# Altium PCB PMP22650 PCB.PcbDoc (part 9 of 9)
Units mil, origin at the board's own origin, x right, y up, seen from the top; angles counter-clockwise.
Board outline 11311 x 5233 mil, 8 copper layers (Layer 1, Layer 2, Layer 3, Layer 4, Layer 5, Layer 6, Layer 7, Layer 8), stack 88.6 mil thick; 633 components, 410 nets, 2503 pads, 1993 vias.
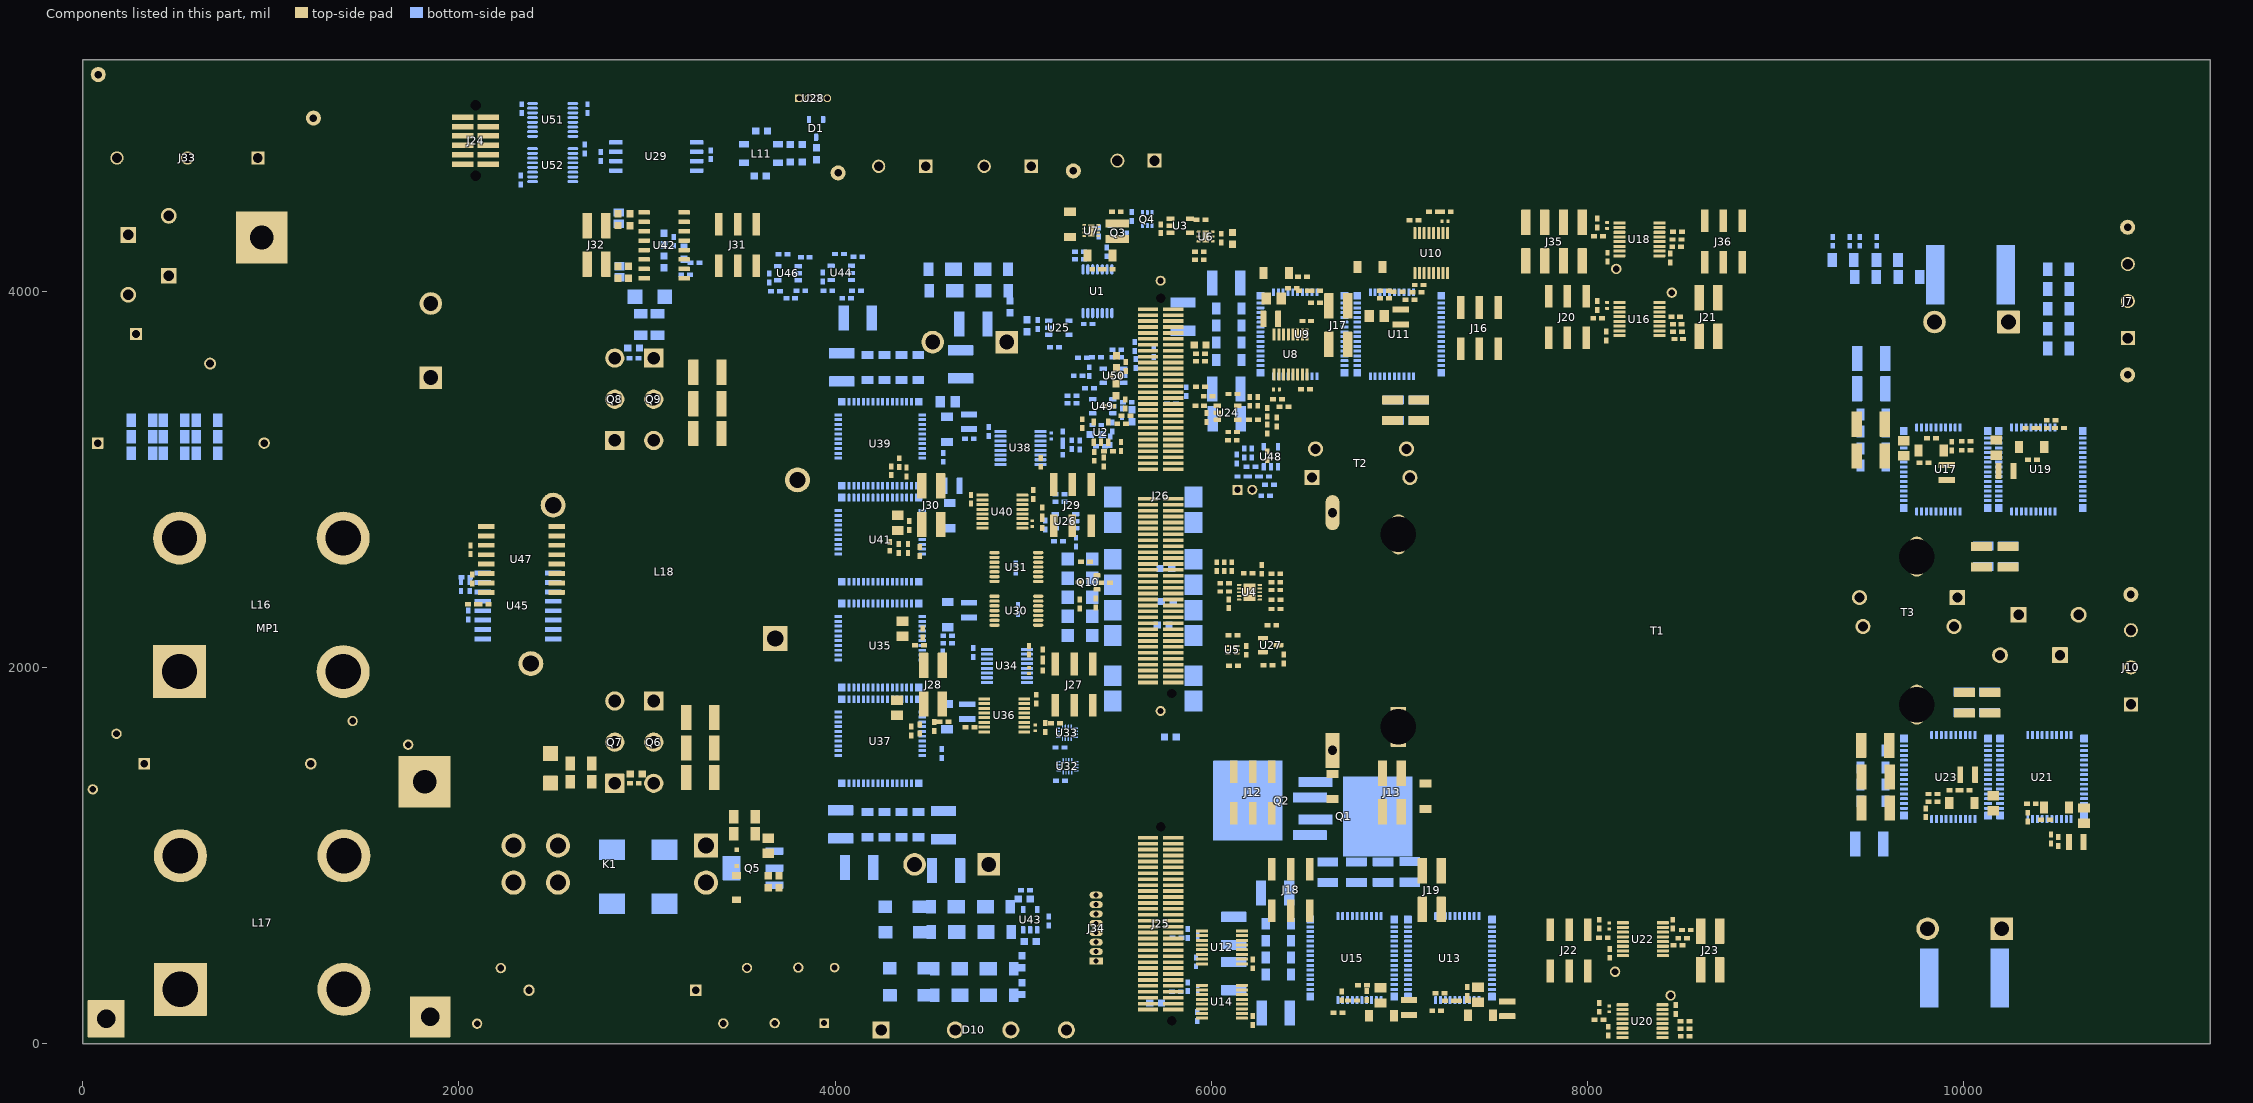
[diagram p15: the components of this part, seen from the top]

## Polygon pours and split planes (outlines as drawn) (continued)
SW_C_RES on Layer 2 "NONET_L-01_P-001" (solid, remove dead copper, pour order 366): 10325.29,2450 9913.23,2450 9913.23,2604 10324.97,2604

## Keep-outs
Layer 1:
  circle w1: c7548.54,327.29 r10
  circle w1: c7527.27,327.29 r10
  circle w1: c6310,412 r10
  circle w1: c6291,412 r10
  circle w1: c6273,412 r10
  circle w1: c6310,504 r10
  circle w1: c6291,505 r10
  circle w1: c6273,505 r10
  circle w1: c6273,593 r10
  circle w1: c6291,593 r10
  circle w1: c6310,593 r10
  circle w19.68: c4665.9,2514.99 r98.43
  circle w19.68: c3813.46,647.46 r98.43
  circle w19.68: c3379.18,3901.84 r98.43
  circle w19.68: c1247.18,3089.84 r98.43
  circle w19.68: c10471.89,2626.17 r98.43
  circle w19.68: c7448.57,4317.63 r98.43
  circle w19.68: c9104.8,145.99 r98.43
  circle w19.68: c6029.84,891.93 r98.43
  circle w19.68: c6343.43,2734.37 r98.43
  circle w19.68: c6576.2,3348.75 r98.43
  circle w19.68: c7800.73,214.14 r98.43
  circle w19.68: c6285.57,1786.37 r98.43
  circle w19.68: c9071.27,4171.97 r98.43
  circle w19.68: c10392.8,1838.99 r98.43
Layer 3:
  circle w1: c8447.91,3994.61 r30
  circle w1: c4352.81,2310.97 r10
  circle w1: c4352.81,2289.69 r10
  circle w1: c4422,2171 r10
  circle w1: c4343,2131.24 r10
  circle w1: c4365.27,2131.24 r10
  circle w1: c4413.27,2024.28 r10
  circle w1: c4413.27,2001.49 r10
  circle w1: c6275,688 r10
  circle w1: c6257,688 r10
  circle w1: c6257,664 r10
  circle w1: c6309,412 r10
  circle w1: c6292,412 r10
  circle w1: c6273,412 r10
  circle w1: c6309,504 r10
  circle w1: c6292,504 r10
  circle w1: c6273,504 r10
  circle w1: c6273,593 r10
  circle w1: c6291,593 r10
  circle w1: c6310,593 r10
  circle w1: c9258.27,4167.6 r7
Layer 5:
  circle w1: c10457.46,1232.86 r10
  circle w1: c10457.24,1252.37 r10
  circle w1: c10606.27,1303.88 r10
  circle w1: c10584.99,1303.88 r10
  circle w1: c7264.16,750.08 r10
  circle w1: c7264.16,771.71 r10
  circle w1: c4352.81,2310.97 r10
  circle w1: c4352.81,2289.69 r10
  circle w1: c4638.27,3332.6 r10
  circle w1: c4638.27,3352.6 r10
  circle w1: c4468.97,3067.17 r10
  circle w1: c4424.17,3214 r10
  circle w1: c4658.27,3332.6 r10
  circle w1: c4658.27,3352.6 r10
  circle w1: c4424.17,3308.36 r10
  circle w1: c4424.17,3262 r10
  circle w1: c4426,3117 r10
  circle w1: c4448.09,3067.17 r10
  circle w1: c4761,1948 r10
  circle w1: c4762,2098 r10
  circle w1: c4343,2131.24 r10
  circle w1: c4365.27,2131.24 r10
  circle w1: c4413.27,2024.28 r10
  circle w1: c4413.27,2001.49 r10
  circle w1: c10572,1132 r10
  circle w1: c10551,1132 r10
  circle w1: c10314,1196 r10
  circle w1: c10477.46,1232.86 r10
  circle w1: c10477.24,1252.37 r10
  circle w1: c7443,344 r10
  circle w1: c7443,365 r10
  circle w1: c7306,271 r10
  circle w1: c7249,306 r10
  circle w1: c6219,581 r10
  circle w1: c6241,450 r10
  lines w1: 4431.7,2173.43 ccw(c4422,2171) 4431.95,2172 ; 4648.97,2341.06 ccw(c4639.27,2338.63) 4649.22,2339.63 ; 4648.97,2363.85 ccw(c4639.27,2361.43) 4649.22,2362.42 ; 4667.7,2341.43 ccw(c4658,2339) 4667.95,2340 ; 4667.7,2364.43 ccw(c4658,2362) 4667.95,2363
Layer 6:
  circle w1: c10457.46,1232.86 r10
  circle w1: c10457.24,1252.37 r10
  circle w1: c9850.69,3174.56 r10
  circle w1: c8655,3689 r10
  circle w1: c8655,3710 r10
  circle w1: c8423,3791 r10
  circle w1: c8426,3945 r10
  circle w1: c10584.99,1303.88 r10
  circle w1: c10606.27,1303.88 r10
  circle w1: c7264.16,771.71 r10
  circle w1: c7264.16,750.08 r10
  circle w1: c4325.4,2310.97 r10
  circle w1: c4325.4,2289.69 r10
  circle w1: c8442,59 r10
  circle w1: c8491,209 r10
  circle w1: c8745,432 r10
  circle w1: c8745,452 r10
  circle w1: c10314.51,1195.86 r10
  circle w1: c10572.48,1132.31 r10
  circle w1: c10551,1132 r10
  circle w1: c10477.46,1232.86 r10
  circle w1: c10477.24,1252.37 r10
  circle w1: c9990,3231 r10
  circle w1: c9851,3199 r10
  circle w1: c9723,3157 r10
  circle w1: c9723,3135 r10
  circle w1: c7443,344 r10
  circle w1: c7443,365 r10
  circle w1: c7249,306 r10
  circle w1: c6241,450 r10
  circle w1: c8655,4132 r7
  circle w1: c8752,4132 r7
Layer 2:
  circle w1: c4352.81,2289.69 r10
  circle w1: c4352.81,2310.97 r10
  circle w1: c4638.27,3352.6 r10
  circle w1: c4658.27,3352.6 r10
  circle w1: c4658.27,3332.6 r10
  circle w1: c4638.27,3332.6 r10
  circle w1: c4468.97,3067.17 r10
  circle w1: c4448.09,3067.17 r10
  circle w1: c4426,3117 r10
  circle w1: c4424.17,3214 r10
  circle w1: c4424.17,3262 r10
  circle w1: c4424.17,3308.36 r10
  circle w1: c4639.27,2338.63 r10
  circle w1: c4639.27,2361.43 r10
  circle w1: c4658,2362 r10
  circle w1: c4658,2339 r10
  circle w1: c4761,2097 r10
  circle w1: c4413.27,2001.49 r10
  circle w1: c4413.27,2024.28 r10
  circle w1: c4343,2131.24 r10
  circle w1: c4365.27,2131.24 r10
  circle w1: c4422,2171 r10
Layer 7:
  circle w1: c7264.16,771.71 r10
  circle w1: c7264.16,750.08 r10
  circle w1: c6241,450 r10
Layer 8:
  circle w1: c6219,581 r10
  circle w1: c6241,450 r10
  circle w29.53: c6576.2,3348.75 r103.35
  circle w29.53: c4665.9,2514.99 r103.35
  circle w29.53: c3813.46,647.46 r103.35
  circle w29.53: c3379.18,3901.84 r103.35
  circle w29.53: c1247.18,3089.84 r103.35
  circle w29.53: c10471.89,2626.17 r103.35
  circle w29.53: c7448.57,4317.63 r103.35
  circle w29.53: c9104.8,145.99 r103.35
  circle w29.53: c6029.84,891.93 r103.35
  circle w29.53: c6343.43,2734.37 r103.35
  circle w29.53: c7800.73,214.14 r103.35
  circle w29.53: c6285.57,1786.37 r103.35
  circle w29.53: c9071.27,4171.97 r103.35
  circle w29.53: c10392.8,1838.99 r103.35
Keep-Out Layer:
  circle w25: c4665.9,2514.99 r75.51
  circle w25: c3813.46,647.46 r75.51
  circle w25: c3379.18,3901.84 r75.51
  circle w25: c1247.18,3089.84 r75.51
  circle w25: c10471.89,2626.17 r75.51
  circle w25: c7448.57,4317.63 r75.51
  circle w25: c9104.8,145.99 r75.51
  circle w25: c6285.57,1786.37 r75.51
  circle w23.62: c10551.18,118.11 r55.12
  circle w23.62: c10551.18,4330.71 r55.12
  circle w25: c6029.84,891.93 r75.51
  circle w25: c6343.43,2734.37 r75.51
  circle w25: c6576.2,3348.75 r75.51
  circle w25: c7800.73,214.14 r75.51
  circle w25: c9071.27,4171.97 r75.51
  circle w25: c10392.8,1838.99 r75.51
  text ".Layer_Name" at 577,-858.49 h60

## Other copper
Layer 1:
  text ".Layer_Name" at 577,-858.49 h60
Layer 3:
  pour cut-out: 6657,4191 6657,4187 6272,4187 6272,3760 6307,3725 6611,3725 6657,3771 6657,4191 6661,4191 6661,3770 6612,3721 6305,3721 6268,3758 6268,4191
  pour cut-out: 6667,704 6667,698 6135,698 6133,371 6660.03,371 6705.87,416.84 7125.38,416.84 7125.38,113.84 7520.5,105.53 7523.57,289.8 7504,344.17 7504,653 7330.28,826.72 6666.99,831.64 6667,704 6657.84,705 6657.84,836.84 7332.74,835.52 7510.13,658.13 7510.13,349.52 7529.35,293.97 7529.35,96.68 7117.07,105.53 7115.29,406.75 6707.84,406.75 6662.29,363.99 6129,363 6129,704
  region net PGND: 5542,3698.08
  region net PGND: 5542,3698.08
  region net PGND: 5542,3698.08
  region net PGND: 5542,3698.08
  region net PGND: 5542,3698.08
  region net PGND: 5542,3698.08
  region net PGND: 5542,3698.08
  region net PGND: 5542,3698.08
  region net PGND: 5542,3698.08
  region net PGND: 5542,3698.08
  region net PGND: 5542,3698.08
  region net PGND: 5542,3698.08
  region net PGND: 5542,3698.08
  region net PGND: 5542,3698.08
  region net PGND: 5542,3698.08
  region net PGND: 5542,3698.08
  region net PGND: 5542,3698.08
  region net PGND: 5542,3698.08
  region net PGND: 5542,3698.08
  region net PGND: 5542,3698.08
  region net PGND: 5542,3698.08
  region net PGND: 5542,3698.08
  region net PGND: 5542,3698.08
  region net PGND: 5542,3698.08
  region net PGND: 5542,3698.08
  region net PGND: 5542,3698.08
  region net PGND: 5542,3698.08
  region net PGND: 5542,3698.08
  region net PGND: 5542,3698.08
  region net PGND: 5542,3698.08
  region net PGND: 5542,3698.08
  region net PGND: 5542,3698.08
  region net PGND: 5542,3698.08
  region net PGND: 5542,3698.08
  region net PGND: 5542,3698.08
  region net PGND: 5542,3698.08
  region net PGND: 5542,3698.08
  region net PGND: 5542,3698.08
  region net PGND: 5542,3698.08
  region net PGND: 5542,3698.08
  region net PGND: 5542,3698.08
  region net PGND: 5542,3698.08
  region net PGND: 5542,3698.08
  region net PGND: 5542,3698.08
  region net PGND: 5542,3698.08
  region net PGND: 5542,3698.08
  region net PGND: 5542,3698.08
  region net PGND: 5542,3698.08
  region net PGND: 5542,3698.08
  region net PGND: 5542,3698.08
  region net PGND: 5542,3698.08
  region net PGND: 5542,3698.08
  region net PGND: 5542,3698.08
  region net PGND: 5542,3698.08
  region net PGND: 5542,3698.08
  region net PGND: 5542,3698.08
  region net PGND: 5542,3698.08
  region net PGND: 5542,3698.08
  region net PGND: 5542,3698.08
  region net PGND: 5542,3698.08
  region net PGND: 5542,3698.08
  region net PGND: 5542,3698.08
  region net PGND: 5542,3698.08
  region net PGND: 5542,3698.08
  region net PGND: 5542,3698.08
  region net PGND: 5542,3698.08
  region net PGND: 5542,3698.08
  region net PGND: 5542,3698.08
  region net PGND: 5542,3698.08
  region net PGND: 5542,3698.08
  region net PGND: 5542,3698.08
  region net PGND: 5542,3698.08
  region net PGND: 5542,3698.08
  region net PGND: 5542,3698.08
  region net PGND: 5542,3698.08
  region net PGND: 5542,3698.08
  region net PGND: 5542,3698.08
  region net PGND: 5542,3698.08
  region net PGND: 5542,3698.08
  region net PGND: 5542,3698.08
  region net PGND: 5542,3698.08
  region net PGND: 5542,3698.08
  region net PGND: 5542,3698.08
  region net PGND: 5542,3698.08
  region net PGND: 5542,3698.08
  region net PGND: 5542,3698.08
  region net PGND: 5542,3698.08
  region net PGND: 5542,3698.08
  region net PGND: 5542,3698.08
  region net PGND: 5542,3698.08
  region net PGND: 5542,3698.08
  region net PGND: 5542,3698.08
  region net PGND: 5542,3698.08
  region net PGND: 5542,3698.08
  region net PGND: 5542,3698.08
  region net PGND: 5542,3698.08
  region net PGND: 5542,3698.08
  region net PGND: 5542,3698.08
  region net PGND: 5542,3698.08
  region net PGND: 5542,3698.08
  region net PGND: 5542,3698.08
  region net PGND: 5542,3698.08
  region net PGND: 5542,3698.08
  region net PGND: 5542,3698.08
  region net PGND: 5542,3698.08
  region net PGND: 5542,3698.08
  region net PGND: 5542,3698.08
  region net PGND: 5542,3698.08
  region net PGND: 5542,3698.08
  region net PGND: 5542,3698.08
  region net PGND: 5542,3698.08
  region net PGND: 5542,3698.08
  region net PGND: 5542,3698.08
  region net PGND: 5542,3698.08
  region net PGND: 5542,3698.08
  region net PGND: 5542,3698.08
  region net PGND: 5542,3698.08
  region net PGND: 5542,3698.08
  region net PGND: 5542,3698.08
  region net PGND: 5542,3698.08
  region net PGND: 5542,3698.08
  region net PGND: 5542,3698.08
  region net PGND: 5542,3698.08
  region net PGND: 5542,3698.08
  region net PGND: 5542,3698.08
  region net PGND: 5542,3698.08
  region net PGND: 5542,3698.08
  region net PGND: 5542,3698.08
  region net PGND: 5542,3698.08
  region net PGND: 5542,3698.08
Layer 4:
  pour cut-out: 4446.18,1892.05 4758.18,1892.05 4851,1799.24 4851,1655.87 4709.18,1514.05 4363.18,1514.05 4363.18,1809.05
  pour cut-out: 4413,2967.5 4725,2967.5 4781,2911.5 4781,2694.5 4676,2589.5 4330,2589.5 4263,2656.5 4263,2817.5
  pour cut-out: 6638.18,283.48 6680.37,325.67 6950.98,325.67 6990.17,286.48 6990.17,130.48 6960.17,100.48 6661.17,100.48 6638.17,123.48
  pour cut-out: 6779.18,4068.48 6821.37,4110.67 7091.98,4110.67 7131.17,4071.48 7131.17,3915.48 7101.17,3885.48 6802.17,3885.48 6779.17,3908.48
  pour cut-out: 10180.5,3357 10222.69,3399.19 10493.31,3399.19 10532.5,3360 10532.5,3204 10413.5,3085 10237,3085 10180.5,3141.5
  pour cut-out: 9808,1284 9881,1357 10090,1357 10160,1287 10160,1131 10130,1101 9831,1101 9808,1124
Layer 5:
  pour cut-out: 4430.37,1878.31 4742.37,1878.31 4853,1767.68 4853,1659.95 4693.37,1500.31 4347.37,1500.31 4347.37,1795.31
  pour cut-out: 4428,2965.77 4740,2965.77 4796,2909.77 4796,2692.77 4691,2587.77 4345,2587.77 4278,2654.77 4278,2815.77
  pour cut-out: 6779.18,4068.48 6821.37,4110.67 7091.98,4110.67 7131.17,4071.48 7131.17,3915.48 7101.17,3885.48 6802.17,3885.48 6779.17,3908.48
  pour cut-out: 10180.5,3357 10222.69,3399.19 10493.31,3399.19 10532.5,3360 10532.5,3204 10416.5,3088 10243,3088 10180.5,3150.5
  pour cut-out: 9808,1284 9879,1355 10092,1355 10160,1287 10160,1131 10130,1101 9831,1101 9808,1124
Layer 6:
  pour cut-out: 6779.18,4068.48 6821.37,4110.67 7091.98,4110.67 7131.17,4071.48 7131.17,3915.48 7101.17,3885.48 6802.17,3885.48 6779.17,3908.48
  pour cut-out: 10180.5,3357 10222.69,3399.19 10493.31,3399.19 10532.5,3360 10532.5,3204 10413.5,3085 10242,3085 10180.5,3146.5
  pour cut-out: 9808,1284 9881,1357 10090,1357 10160,1287 10160,1131 10130,1101 9831,1101 9808,1124
Layer 8:
  pour cut-out: 4304,3072 4304,3309 cw(c4316,3309) 4328,3309 4328,3072 cw(c4316,3072)
  pour cut-out: 4294,2598 4294,2835 cw(c4306,2835) 4318,2835 4318,2598 cw(c4306,2598)
  pour cut-out: 4290,2003 4290,2240 cw(c4302,2240) 4314,2240 4314,2003 cw(c4302,2003)
  pour cut-out: 4318,1502 4318,1739 cw(c4330,1739) 4342,1739 4342,1502 cw(c4330,1502)
  pour cut-out: 7202,408 7439,408 cw(c7439,396) 7439,384 7202,384 cw(c7202,396)
  pour cut-out: 6640,367 6877,367 cw(c6877,355) 6877,343 6640,343 cw(c6640,355)
  pour cut-out: 6852,3872 7089,3872 cw(c7089,3860) 7089,3848 6852,3848 cw(c6852,3860)
  pour cut-out: 6340,3877 6577,3877 cw(c6577,3865) 6577,3853 6340,3853 cw(c6340,3865)
  pour cut-out: 9803,3122 10040,3122 cw(c10040,3110) 10040,3098 9803,3098 cw(c9803,3110)
  pour cut-out: 10262,3110 10499,3110 cw(c10499,3098) 10499,3086 10262,3086 cw(c10262,3098)
  pour cut-out: 9780.4,1376.13 10017.4,1376.14 cw(c10017.4,1364.14) 10017.4,1352.14 9780.4,1352.14 cw(c9780.4,1364.13)
  pour cut-out: 10305,1338 10542,1338 cw(c10542,1326) 10542,1314 10305,1314 cw(c10305,1326)
  text ".Layer_Name" at 577,-858.49 h60

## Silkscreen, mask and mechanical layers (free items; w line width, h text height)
Top Overlay:
  lines w10: 0,4448.82 0,0 10669.29,0 ; 0.71,4449.52 10670,4449.52 10670,0.71 ; 242,3983 242,4156 ; 456,4225 456,4402 ; 4094,4998 4094,5209 4364,5209 5136,5209 5470,5209 6001,5209 6001,4910 5372,4910 5372,5081 ; 4095,4995 5295,4995 5295,5016.5 5295,5081 6001,5081 ; 5721,2560 5722,2561 ; 5942,1904 5942,1633 6125,1633 ; 5945,1905 6127,1905 6127,1734 6127,1635 ; 6126,1904 6394,2172 6394,2292 ; 10187,2069 10364,2069 ; 10433,2283 10606,2283 ; 11302,1692 11120,1692 11120,1863 11120,4559 11305,4559 11305,1693 ; 6394,2292 6397,2295 6397,2525 6396,2526 6287,2526 6287,2292 6394,2292 ; 25,5023 25,5215 196,5215 1963,5215 1963,5023 25,5023
  text "90 VAC - 265 VAC, 50 Hz -60 Hz" at 163,5127.99 h60
  text "250 VDC - 450 VDC, 6600 W, 30 A" at 4147,5120.99 h60
  text "CAN" at 3800,5103 h60
  text "6600 W, 30 A" at 1173,5040.99 h60
  text "LINE" at 31,5032 h60
  text "NEUTRAL" at 310,5032 h60
  text "EARTH" at 739,5032 h60
  text "ETAS" at 1987,5032 h60
  text "DCLINK" at 4198,5012 h60
  text "PGND" at 4775,5012 h60
  text "+" at 4121,5002 h60
  text "+" at 4552.04,5002 h60
  text "-" at 4685.35,5002 h60
  text "-" at 5056,5002 h60
  text "12 V, 2 A" at 5401,4982.99 h60
  text "-" at 5493.26,4905 h60
  text "+" at 5671,4905 h60
  text "'.PRJ_Number'.PCB_Rev" at 9668,4850 h108.27
  text "NEUTRAL" at 1330.27,4820.6 h60
  text "PMP22712" at 3591,4317 h45
  text "PMP22773" at 8912.52,4305.85 h45
  text "-" at 11184.25,4124 h60 r90
  text "BATT_RTN" at 11268.51,4080.1 h60 r90
  text "-" at 11184.25,3923.5 h60 r90
  text "PMP22712" at 8770,3756 h45
  text "PMP22712" at 6831.57,3736.49 h45
  text "-" at 11184.25,3723 h60 r90
  text "SGND" at 10835,3421 h60
  text "PMP22712" at 4666,2672 h45
  text "+" at 11134.27,2167.6 h60
  text "250 VDC - 450 VDC, 6600 W, 30 A" at 11276.01,2097 h60 r90
  text "+" at 11134.27,1967.17 h60
  text "PMP22712" at 4645,1865 h45
  text "+" at 11134.27,1766.73 h60
  text "VBATT" at 11281,1737 h60 r90
  text "PMP22742" at 6421,1293 h45
  text "PMP22712" at 6699,809 h45
  text "PMP22712" at 8802,481 h45
  text ".Layer_Name" at 577,-858.49 h60
Bottom Overlay:
  lines w10: 0,4448.82 0,0 10669.29,0 ; 0.71,4449.52 10670,4449.52 10670,0.71
  text ".Layer_Name" at 577,-858.49 h60
Top Paste:
  text ".Layer_Name" at 577,-858.49 h60
Bottom Paste:
  text ".Layer_Name" at 577,-858.49 h60
Top Solder:
  text ".Layer_Name" at 577,-858.49 h60
  text ".Layer_Name" at 577,-858.49 h60
Bottom Solder:
  text ".Layer_Name" at 577,-858.49 h60
Drill Guide:
  text ".Layer_Name" at 577,-858.49 h60
M1 Board Outline:
  drawing of 328 lines, arcs and shapes, not listed
  text ".Layer_Name" at 577,-858.49 h60
M2 Board Dimensions:
  rectangle: 0,-275 125,-150
  rectangle: 125,-400 500,-275
  lines w7: 0,-275 1000,-275 ; 125,-400 125,-150 ; 250,-400 250,-150 ; 500,-400 500,-150 ; 750,-400 750,-150 ; 0,-400 1000,-400 1000,-150 0,-150 0,-400
  text ".Layer_Name" at 577,-858.49 h60
M3 3D STEP Top:
  text ".Layer_Name" at 577,-858.49 h60
M4 3D STEP Bottom:
  text ".Layer_Name" at 577,-858.49 h60
M5 Assembly Top:
  circle w10: c1259.84,1129.08 r39.37
  circle w10: c1254.1,4902.46 r39.37
  lines w10: -292,-930.17 6308,-930.17 ; -292,-726.83 6310,-726.83 ; -292,-523.5 -292,-1133.5 3713,-1133.5 6310,-1133.5 6310,-523.5 -291.5,-523.5 -291.5,-1133.5 1284,-1133.5 ; 2173,-1133.5 2173,-523.5 ; 3440,-726.83 3440,-523.5 ; 4280,-726.83 4280,-523.5 ; 4902,-1140 4902,-937.17 ; 7050,3043 7053,3043 ; 7445,3043 7445,2808 8970,2808 8969,2809 8969,3197 7445,3197 7445,3046 ; 7727,2189 7727,2542 9244,2542 9244,2189 7727,2189
  lines w50: 6806,3290 7053,3043 7447,3043 ; 6882,2875 7050,3043 ; 9247,2543 9623,2543 ; 9399,2548 9507,2656 9843,2656 9964,2535
  text "Install 12 AWG solid core" at 7526.91,3076 h60
  text "wire in these holes." at 7526.91,2950.81 h60
  text "Thread wire through T2." at 7526.91,2845.6 h60
  text "Install 12 AWG solid core" at 7762,2430 h60
  text "wire in these holes." at 7755,2348 h60
  text "Thread wire through T3." at 7762,2245.99 h60
  text "COMPONENTS MARKED 'DNP' SHOULD NOT BE POPULATED." at 1153.5,-318.5 h60
  text "ASSEMBLY VARIANT:" at 1153,-434 h60
  text ".VariantName" at 2189,-434 h60
  text "PCB VIEWED FROM TOP SIDE" at -228.5,-655.67 h60
  text "BOARD #:" at 2248,-655.67 h60
  text ".PRJ_Number" at 2793.5,-655.67 h60
  text "REV:" at 3638,-655.67 h60
  text ".PCB_Rev" at 3929.5,-655.67 h60
  text "SVN REV:" at 4476,-655.67 h60
  text ".VersionControl_RevNumber" at 4982,-655.67 h60
  text "TID #:" at 2248,-859 h60
  text ".TID" at 2793.5,-859 h60
  text "PLOT NAME =" at -228.5,-1064.34 h60
  text ".plot_File_Name" at 577,-1064.34 h60
  text "GENERATED    :" at 2250,-1064.34 h60
  text ".Print_Date" at 3119.5,-1064.34 h60
  text ".Print_Time" at 3848.5,-1064.34 h60
  text "TEXAS INSTRUMENTS" at 5113,-1064.34 h60
M6 Assembly Bottom:
  lines w10: -292.5,-727.33 6309.5,-727.33 ; -290.5,-930.67 6309.5,-930.67 ; 1115.5,-1140.5 1115.5,-937.67 ; 1737.5,-727.33 1737.5,-524 ; 2577.5,-727.33 2577.5,-524 ; 3844.5,-1134 3844.5,-524 ; 4733.5,-1134 6309,-1134 6309,-524 -292.5,-524 -292.5,-1134 2304.5,-1134 6309.5,-1134 6309.5,-524
  text "Trim all leads to within 2 mm" at 6203,5094 h100
  text "of the bottom of the board surface." at 6203,4929 h100
  text "Q6, Q7, Q8, and Q 9:" at 306,1817.99 h60
  text "Bottom of package" at 306,1703.99 h60
  text "should face cold plate." at 306,1589.99 h60
  text "COMPONENTS MARKED 'DNP' SHOULD NOT BE POPULATED." at 6102,-318 h60
  text ".VariantName" at 5058,-434 h60
  text "ASSEMBLY VARIANT:" at 6097,-434 h60
  text ".VersionControl_RevNumber" at 1035.5,-656.17 h60
  text "SVN REV:" at 1541.5,-656.17 h60
  text ".PCB_Rev" at 2088,-656.17 h60
  text "REV:" at 2379.5,-656.17 h60
  text ".PRJ_Number" at 3224,-656.17 h60
  text "BOARD #:" at 3769.5,-656.17 h60
  text "PCB VIEWED FROM BOTTOM SIDE" at 6246,-656.17 h60
  text ".TID" at 3224,-859.5 h60
  text "TID #:" at 3769.5,-859.5 h60
  text "TEXAS INSTRUMENTS" at 904.5,-1064.84 h60
  text ".Print_Time" at 2169,-1064.84 h60
  text ".Print_Date" at 2898,-1064.84 h60
  text "GENERATED    :" at 3767.5,-1064.84 h60
  text ".plot_File_Name" at 5440.5,-1064.84 h60
  text "PLOT NAME =" at 6246,-1064.84 h60
M9 Title Sheet:
  drawing of 57 lines, arcs and shapes, not listed
  text "1" at 916.17,9210.31 h79.98
  text "2" at 3767.76,9210.31 h79.98
  text "3" at 6612.14,9210.31 h79.98
  text "4" at 9476.31,9210.31 h79.98
  text "5" at 12331.71,9210.31 h79.98
  text "6" at 15193.98,9210.31 h79.98
  text "A" at -405.09,7904.3 h79.98
  text "A" at 16505.71,7904.3 h79.98
  text "B" at -405.09,5184.86 h79.98
  text "B" at 16505.71,5184.86 h79.98
  text "C" at -405.09,2471.13 h79.98
  text "C" at 16505.71,2471.13 h79.98
  text "PROJECT TITLE:" at 13032.14,344.71 h51.42
  text ".PRJ_Title" at 13089.27,192.37 h79.98
  text "DESIGNED FOR:" at 13032.14,0.78 h51.42
  text ".PRJ_Customer" at 13089.27,-159.18 h79.98
  text "D" at -405.09,-236.88 h79.98
  text "D" at 16505.71,-236.88 h79.98
  text "FILE NAME:" at 13032.14,-342 h51.42
  text ".PCB_File_Name_No_Path" at 13089.27,-479.12 h79.98
  text "Texas Instruments (TI) and/or its licensors do not warrant the accuracy or completeness of this specification" at 7353.88,-664.04 h51.42
  text "ENGINEER:" at 13032.14,-673.36 h51.42
  text "LAYOUT BY:" at 14751.79,-673.36 h51.42
  text "or any information contained therein. TI and/or its licensors do not warrant that this design will meet" at 7302.48,-792.77 h51.42
  text ".PRJ_Engineer" at 13089.27,-850.46 h79.98
  text ".PCB_Layout" at 14809.49,-850.46 h79.98
  text "the specifications, will be suitable for your application or fit for any particular purpose, or will operate in" at 7302.48,-921.51 h51.42
  text ".Layer_Name" at 730.1,-953.3 h68.56
  text "ALTIUM DESIGNER VERSION:" at 14751.79,-1027.58 h51.42
  text "an implementation. TI and/or its licensors do not warrant that the design is production worthy. You should" at 7302.48,-1050.24 h51.42
  text "completely validate and test your design implementation to confirm the system functionality for your application." at 7353.88,-1178.97 h51.42
  text ".print_Scale" at 13089.27,-1179.92 h79.98
  text ".Application_BuildNumber" at 14809.49,-1179.92 h79.98
  text "1" at 916.17,-1416.07 h79.98
  text "2" at 3767.76,-1416.07 h79.98
  text "3" at 6612.14,-1416.07 h79.98
  text "4" at 9476.31,-1416.07 h79.98
  text "5" at 12331.71,-1416.07 h79.98
  text "6" at 15193.98,-1416.07 h79.98
M10 Fab Notes:
  drawing of 189 lines, arcs and shapes, not listed
  text "DESIGN INFORMATION" at 14409.12,6616.17 h60
  text "MIN. TRACK WIDTH:" at 13764.56,6484.05 h60
  text "8" at 14860.8,6484.05 h60
  text "MIL" at 15015.56,6484.05 h60
  text "MIN. CLEARANCE:" at 13764.56,6359.92 h60
  text "0.2" at 14800.8,6359.93 h60
  text "mm" at 15015.56,6359.92 h60
  text "MIN. VIA PAD SIZE:" at 13764.56,6235.8 h60
  text "24" at 14830.81,6235.8 h60
  text "MIL" at 15015.56,6235.8 h60
  text "0.05mm (2MIL)" at 14459.56,6105.9 h60
  text "MINIMUM ANNULAR RING" at 13435.33,6097.67 h60
  text "EXTERNAL" at 15167.56,6097.67 h60
  text "PER" at 13635.33,5987.55 h60
  text "IPC-D-275 CLASS 2 LEVEL C" at 13855.33,5987.54 h60
  text "MIL, HOLES" at 15343.56,5887.07 h60
  text "+/-" at 14951.1,5878.48 h60
  text "+/-" at 15805.1,5878.48 h60
  text "REGISTRATION TOLERANCES:" at 13435.33,5877.42 h60
  text "METAL" at 14635.1,5877.42 h60
  text "5" at 15211.3,5877.42 h60
  text "3" at 16044.3,5877.42 h60
  text "MIL" at 16160.56,5877.42 h60
  text "HOLE SIZE TOLERANCE (UNLESS OTHERWISE SPECIFIED):" at 13435.33,5779.1 h60
  text "+/-" at 15805.1,5776.23 h60
  text "3" at 16044.3,5775.17 h60
  text "MIL" at 16160.56,5775.17 h60
  text "MATERIAL:" at 13360.56,5637.52 h60
  text "FR-4 High Tg" at 14347,5509 h60
  text "X" at 14202.56,5501.01 h60
  text "FR-408" at 13781.56,5496.49 h60
  text "OTHER" at 15269.56,5496.49 h60
  text "89.4 MIL (2.3mm) +/-10%" at 14101.66,5353.46 h60
  text "X" at 13981.56,5351.01 h60
  text "THICKNESS:" at 13435.33,5345.24 h60
  text "OTHER" at 15386.56,5345.24 h60
  text "TOLERANCE:" at 13435.33,5206.92 h60
  text "X" at 14283.56,5206.92 h60
  text "ANSI IPC-6012 TYPE 3 CLASS 2" at 14461.58,5206.92 h60
  text "OTHER +/-" at 14461.56,5062.73 h60
  text "BOW & TWIST:" at 13435.33,4917.54 h60
  text "X" at 14283.56,4917.54 h60
  text "ANSI IPC-6012 TYPE 3 CLASS 2" at 14461.58,4917.54 h60
  text "OTHER +/-" at 14461.56,4770.85 h60
  text "DRILLING:" at 13360.56,4640.23 h60
  text "NC_DRILL FILES" at 15121.56,4535.04 h60
  text "REFERENCE:" at 13435.33,4531.1 h60
  text "X" at 14092.56,4531.01 h60
  text "AS SHOWN" at 14270.56,4531.1 h60
  text "X" at 14993.56,4531.1 h60
  text "OTHER" at 15419.56,4388.85 h60
  text "PTH COPPER THICKNESS:" at 13435.01,4385.32 h60
  text "X" at 14574.24,4385.32 h60
  text "20-30 um" at 14702.24,4385.32 h60
  text "BOARD FINISH:" at 13360.56,4237.73 h60
  text "SILKSCREEN:" at 13515.78,4127.6 h60
  text "X" at 14473.56,4127.6 h60
  text "TOP" at 14590.56,4127.6 h60
  text "X" at 14983.56,4127.6 h60
  text "BOTTOM" at 15101.56,4127.6 h60
  text "SILKSCREEN COLOR:" at 13515.78,3972.41 h60
  text "X" at 14472.56,3972.41 h60
  text "WHITE" at 14590.56,3972.41 h60
  text "OTHER" at 15101.56,3972.41 h60
  text "X" at 14603.56,3828.96 h60
  text "GREEN" at 14721.56,3828.96 h60
  text "OTHER" at 15339.56,3828.96 h60
  text "SOLDER RESIST COLOR:" at 13515.78,3822.1 h60
  text "X" at 14603.56,3674.71 h60
  text "MATTE" at 14721.56,3674.71 h60
  text "SEMI-GLOSS" at 15339.1,3674.07 h60
  text "IMMERSION GOLD (ENIG)" at 14421.56,3501.94 h60
  text "ENEPIG" at 15759.1,3494.72 h60
  text "SURFACE FINISH:" at 13360.56,3493.72 h60
  text "X" at 14243.56,3493.72 h60
  text "IMM. TIN/SILVER OR EQUIV" at 13690.1,3356.4 h60
  text "OTHER" at 15121.56,3352.47 h60
  text "ARRAY/PANEL:" at 13360.56,3197.09 h60
  text "CUT AND TRIM PER M1 BOARD OUTLINE" at 14421.56,3188.87 h60
  text "N.C. ROUTE" at 14421.56,3052.9 h60
  text "X" at 15109.56,3052.9 h60
  text "V. SCORE" at 15287.56,3052.9 h60
  text "CERTIFICATION:" at 13360.56,2923.77 h60
  text "MATERIALS AND WORKMANSHIP FOR ALL PCBS" at 14085.56,2923.77 h60
  text "TO MEET OR EXCEED THE REQUIREMENTS OF:" at 14085.56,2829.71 h60
  text "X" at 13723.07,2701.08 h60
  text "ANSI IPC-A-600F CLASS ->" at 13851.06,2701.08 h60
  text "X" at 15499.07,2701.08 h60
  text "2" at 15609.06,2701.08 h60
  text "1" at 15294.06,2699.58 h60
  text "3" at 15963.06,2699.58 h60
  text "X" at 14535.07,2553.39 h60
  text "RoHS" at 14663.06,2553.39 h60
  text "OTHER" at 15307.46,2553.39 h60
  text "PER ORDER" at 15704.52,2553.39 h60
  text "ALL BOARDS MUST MEET OR EXCEED UL94-V0 REQUIREMENTS." at 13388.1,2399.57 h60
  text "PCB MUST BEAR THE UL94V-0 UL REGISTERED MATERIAL ID NUMBER" at 13388.1,2283.5 h60
  text "ADDITIONAL REQUIREMENTS:" at 13360.56,2114.08 h60
  text "MICROSECTION:" at 13435.33,2006.95 h60
  text "YES" at 14341.06,2006.95 h60
  text "REQUIRED" at 15202.56,1862.62 h60
  text "BARE BOARD ELEC. TEST:" at 13435.33,1859.76 h60
  text "NONE" at 14741.06,1859.76 h60
  text "X" at 15084.56,1859.76 h60
  text "PER ORDER" at 15794.56,1859.76 h60
  text "XX MIL VIAS REQUIRE NON-CONDUCTIVE FILL AND PLANARIZE" at 13603.48,1654.82 h59
  text "XX MIL VIAS REQUIRE CONDUCTIVE FILL AND PLANARIZE" at 13611.48,1550.84 h60
  text "OUTER XX MIL TRACES REQUIRE 50 OHM SINGLE-ENDED IMPEDANCE" at 13610.49,1387.46 h58
  text "LAYER 2 & 3 (INNER LAYERS) XX MIL WIDE, XX MIL SPACE / TRACES REQUIRE 100 OHM DIFFERENTIAL IMPEDANCE" at 13602.49,1151.74 h60
  text ".Layer_Name" at 577,-858.49 h60
M11 Gerber Information:
  lines w10: -292,-930.17 6308,-930.17 ; -292,-726.83 6310,-726.83 ; -292,-523.5 -292,-1133.5 3713,-1133.5 6310,-1133.5 6310,-523.5 -291.5,-523.5 -291.5,-1133.5 1284,-1133.5 ; 2173,-1133.5 2173,-523.5 ; 3440,-726.83 3440,-523.5 ; 4280,-726.83 4280,-523.5 ; 4902,-1140 4902,-937.17
  text "ALL ARTWORK VIEWED FROM TOP SIDE" at -228.5,-655.67 h60
  text "BOARD #:" at 2248,-655.67 h60
  text ".PRJ_Number" at 2793.5,-655.67 h60
  text "REV:" at 3638,-655.67 h60
  text ".PCB_Rev" at 3929.5,-655.67 h60
  text "SVN REV:" at 4476,-655.67 h60
  text ".VersionControl_RevNumber" at 4982,-655.67 h60
  text "LAYER NAME =" at -228.5,-858.49 h60
  text "TID #:" at 2248,-859 h60
  text ".TID" at 2793.5,-859 h60
  text "PLOT NAME =" at -228.5,-1064.34 h60
  text ".plot_File_Name" at 577,-1064.34 h60
  text "GENERATED    :" at 2250,-1064.34 h60
  text ".Print_Date" at 3119.5,-1064.34 h60
  text ".Print_Time" at 3848.5,-1064.34 h60
  text "TEXAS INSTRUMENTS" at 5113,-1064.34 h60
M12 Stackup:
  drawing of 941 lines, arcs and shapes, not listed
  text "Layer" at 7329.58,8975 h60
  text "Name" at 7739.49,8975 h60
  text "Material" at 8669.23,8975 h60
  text "Thickness" at 9529,8975 h60
  text "Constant" at 10178.84,8975 h60
  text "Board Layer Stack" at 10748.7,8975 h60
  text "Board Layer Stack 0" at 11868.38,8975 h60
  text "Top Overlay" at 7739.49,8855 h60
  text "Top Solder" at 7739.49,8735 h60
  text "Solder Resist" at 8669.23,8735 h60
  text "0.40mil" at 9529,8735 h60
  text "3.5" at 10178.84,8735 h60
  text "1" at 7329.58,8615 h60
  text "Layer 1" at 7739.49,8615 h60
  text "2.40mil" at 9529,8615 h60
  text "Dielectric 1" at 7739.49,8495 h60
  text "FR-4" at 8669.23,8495 h60
  text "2.80mil" at 9529,8495 h60
  text "4.1" at 10178.84,8495 h60
  text "2" at 7329.58,8375 h60
  text "Layer 2" at 7739.49,8375 h60
  text "1.20mil" at 9529,8375 h60
  text "Dielectric 2" at 7739.49,8255 h60
  text "FR-4" at 8669.23,8255 h60
  text "8.00mil" at 9529,8255 h60
  text "4.1" at 10178.84,8255 h60
  text "3" at 7329.58,8135 h60
  text "Layer 3" at 7739.49,8135 h60
  text "2.40mil" at 9529,8135 h60
  text "Dielectric 3" at 7739.49,8015 h60
  text "FR-4" at 8669.23,8015 h60
  text "9.60mil" at 9529,8015 h60
  text "4.1" at 10178.84,8015 h60
  text "4" at 7329.58,7895 h60
  text "Layer 4" at 7739.49,7895 h60
  text "2.40mil" at 9529,7895 h60
  text "Dielectric 4" at 7739.49,7775 h60
  text "FR-4" at 8669.23,7775 h60
  text "31.00mil" at 9529,7775 h60
  text "4.1" at 10178.84,7775 h60
  text "5" at 7329.58,7655 h60
  text "Layer 5" at 7739.49,7655 h60
  text "2.40mil" at 9529,7655 h60
  text "Dielectric 5" at 7739.49,7535 h60
  text "FR-4" at 8669.23,7535 h60
  text "9.60mil" at 9529,7535 h60
  text "4.1" at 10178.84,7535 h60
  text "6" at 7329.58,7415 h60
  text "Layer 6" at 7739.49,7415 h60
  text "2.40mil" at 9529,7415 h60
  text "Dielectric 6" at 7739.49,7295 h60
  text "FR-4" at 8669.23,7295 h60
  text "8.00mil" at 9529,7295 h60
  text "4.1" at 10178.84,7295 h60
  text "7" at 7329.58,7175 h60
  text "Layer 7" at 7739.49,7175 h60
  text "1.20mil" at 9529,7175 h60
  text "Dielectric 7" at 7739.49,7055 h60
  text "FR-4" at 8669.23,7055 h60
  text "2.80mil" at 9529,7055 h60
  text "4.1" at 10178.84,7055 h60
  text "8" at 7329.58,6935 h60
  text "Layer 8" at 7739.49,6935 h60
  text "2.40mil" at 9529,6935 h60
  text "Bottom Solder" at 7739.49,6815 h60
  text "Solder Resist" at 8669.23,6815 h60
  text "0.40mil" at 9529,6815 h60
  text "3.5" at 10178.84,6815 h60
  text "Bottom Overlay" at 7739.49,6695 h60
  text ".Layer_Name" at 577,-858.49 h60
M13 Component Bodies Top:
  text ".Layer_Name" at 577,-858.49 h60
M14 Component Bodies Bottom:
  text ".Layer_Name" at 577,-858.49 h60
M15 Courtyards Top:
  text ".Layer_Name" at 577,-858.49 h60
M16 Courtyards Bottom:
  text ".Layer_Name" at 577,-858.49 h60
Drill Drawing:
  text ".Layer_Name" at 577,-858.49 h60
M17 Embedded Cavity:
  text ".Layer_Name" at 577,-858.49 h60
M18 Embedded Assembly:
  text ".Layer_Name" at 577,-858.49 h60
M19 Embedded Keepout:
  text ".Layer_Name" at 577,-858.49 h60

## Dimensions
0,0 to 10669.29,0 on M2 Board Dimensions
0,0 to 0,4448.82 on M2 Board Dimensions
0,-400 to 1000,-400 on M2 Board Dimensions
0,0 to 0,5233 on M2 Board Dimensions
0,0 to 11311,0 on M2 Board Dimensions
